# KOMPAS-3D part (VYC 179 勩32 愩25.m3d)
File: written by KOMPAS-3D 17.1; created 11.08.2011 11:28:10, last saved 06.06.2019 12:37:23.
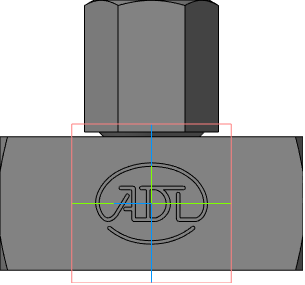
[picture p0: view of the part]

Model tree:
1. Плоскость XY
2. Плоскость ZX
3. Плоскость ZY
4. Ось X
5. Ось Y
6. Ось Z
7. Начало координат
8. Операция без истории:2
